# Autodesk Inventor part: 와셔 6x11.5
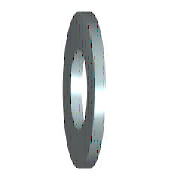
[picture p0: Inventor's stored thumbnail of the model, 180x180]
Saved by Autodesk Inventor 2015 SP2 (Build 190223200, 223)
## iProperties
IsCustomPart: 1
Created: 2012-02
Part Number: 와셔 6x11.5
Material: 강철, 연강
Description: 평면 와셔
Document SubType Name: Modeling
Standard: KS B 1326
Designer: mduedu
Standards Organization: KS
Language: ko-KR
Size Designation: 6x11.5
Categories: <MemberInstance><Categories><Category DisplayName="조임쇠" InternalName="e4da775c-781d-43d5-af7c-5136215cf5a6" Mnemonic="FSTN"><Category DisplayName="와셔" InternalN
Density: 1 g/cm^3
Appearance: 주황색
Author: mduedu
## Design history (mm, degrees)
sketch "스케치"
  geometry: C1 r 5.75 at (0, 0); C2 r 3.2 at (0, 0); 1 further point
  constraints: 2 centre point, 2 coincident
  dimensions: "d0" = 6.4 diameter of C2 (= SD1); "d1" = 11.5 diameter of C1 (= SD2)
extrude "본체" new body sketch "스케치" distance "d2" = 1.6 (= SD); taper "d3" = 0 deg
workaxis "Work Axis1"
workplane "Work Plane1"
body "Solid1"
other parameters: "SD1" = 6.4 [user parameter; used in 1 equation term], "SD2" = 11.5 [user parameter; used in 1 equation term], "SD" = 1.6 [user parameter; used in 1 equation term], "d4" = 0, "d5" = 0, "d6" = 0, "d7" = 0, "NND" = 6 [user parameter]
